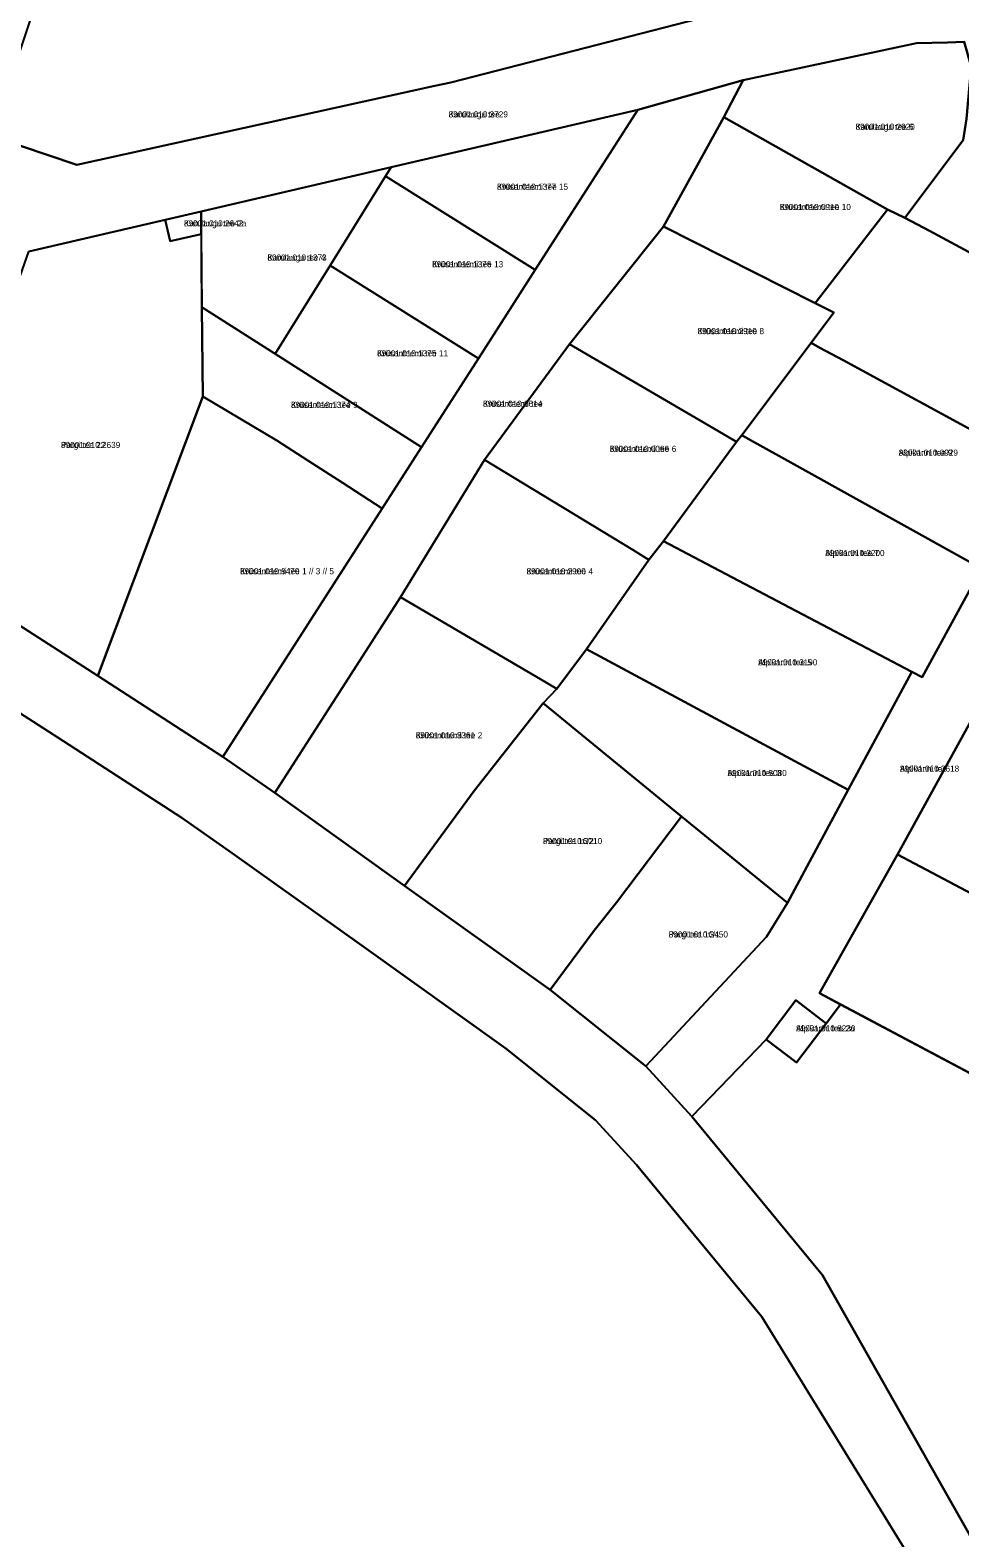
# Model space of a CAD drawing. Extents: x 526849 to 562296, y 6591741 to 6618546.
# Drawn here: x 546990.7 to 547218.3, y 6596402.5 to 6596771.5 of the extents above; entities that cross this region are included whole.
import ezdxf

# ---------------------------------------------------------------- set-up
doc = ezdxf.new("R2010")
doc.units = 0
for name, color, linetype in [('L_AADRESS', 7, 'Continuous'), ('PIIR', 7, 'Continuous'), ('TUNNUS', 7, 'Continuous')]:
    doc.layers.add(name, color=color, linetype=linetype)

msp = doc.modelspace()

# ---------------------------------------------------------------- linework, layer by layer
at = {"layer": 'PIIR'}
for points in [[(547061.75, 6596946.48), (547186.72, 6596892.31), (547160.53, 6596779.59), (547159.62, 6596775.69), (547093.73, 6596758.73), (547089.82, 6596757.87), (547002.16, 6596738.57), (546981.31, 6596745.56), (547032.18, 6596898.67)], [(547165.31, 6596759.28), (547207.75, 6596768.33), (547215.28, 6596768.54), (547219.38, 6596768.66), (547221.14, 6596762.67), (547219.94, 6596749.86), (547219.13, 6596744.63), (547204.87, 6596725.62), (547200.62, 6596727.66), (547160.53, 6596750.27)], [(547219.94, 6596749.86), (547221.14, 6596762.67), (547223.71, 6596763), (547250.81, 6596766.42), (547274.85, 6596760.13), (547256.37, 6596728.15), (547242.55, 6596705.37), (547210.88, 6596722.39), (547204.87, 6596725.62), (547219.13, 6596744.63)], [(547037.89, 6596593.65), (547076.95, 6596654.43), (547086.56, 6596669.47), (547100.49, 6596691.19), (547114.39, 6596712.87), (547139.51, 6596752.04), (547165.31, 6596759.28), (547160.53, 6596750.27), (547145.81, 6596723.49), (547122.79, 6596694.68), (547101.97, 6596666.36), (547081.4, 6596632.76), (547050.6, 6596584.83)], [(547079.14, 6596737.98), (547139.51, 6596752.04), (547114.39, 6596712.87), (547077.77, 6596735.78)], [(547200.62, 6596727.66), (547182.94, 6596704.73), (547145.81, 6596723.49), (547160.53, 6596750.27)], [(547331.64, 6596741.42), (547407.78, 6596725.43), (547411.71, 6596686.07), (547384.86, 6596637.5), (547353.74, 6596639.24), (547342.52, 6596590.2), (547325.97, 6596533.76), (547310.38, 6596483.25), (547295.96, 6596486.54), (547222.61, 6596399.92), (547184.73, 6596466.78), (547152.75, 6596505.65), (547170.93, 6596524.5), (547178.36, 6596518.85), (547185.58, 6596528.42), (547189.1, 6596533.06), (547262.13, 6596494.24), (547270.47, 6596534.11), (547284.34, 6596584.38), (547297.37, 6596630.81), (547280.61, 6596639.69), (547294.38, 6596665.52), (547304.56, 6596660.01), (547315.27, 6596697.05)], [(547032.59, 6596727.14), (547079.14, 6596737.98), (547077.77, 6596735.78), (547064.19, 6596713.91), (547050.74, 6596692.27), (547032.8, 6596703.7)], [(547077.77, 6596735.78), (547114.39, 6596712.87), (547100.49, 6596691.19), (547064.19, 6596713.91)], [(547023.81, 6596725.12), (547032.59, 6596727.14), (547032.61, 6596721.61), (547025.04, 6596719.85)], [(547184.09, 6596693.8), (547181.91, 6596695.01), (547187.49, 6596702.43), (547182.94, 6596704.73), (547200.62, 6596727.66), (547204.87, 6596725.62), (547210.88, 6596722.39), (547242.55, 6596705.37), (547255.38, 6596698.36), (547237.2, 6596664.95), (547189.8, 6596690.72)], [(546990.46, 6596717.38), (547023.81, 6596725.12), (547025.04, 6596719.85), (547032.61, 6596721.61), (547032.8, 6596703.7), (547032.98, 6596681.88), (547007.29, 6596613.51), (546963.62, 6596641.59)], [(547145.81, 6596723.49), (547182.94, 6596704.73), (547187.49, 6596702.43), (547181.91, 6596695.01), (547164.92, 6596672.42), (547163.69, 6596670.76), (547159.06, 6596673.47), (547122.79, 6596694.68)], [(547064.19, 6596713.91), (547100.49, 6596691.19), (547086.56, 6596669.47), (547050.74, 6596692.27)], [(547032.8, 6596703.7), (547050.74, 6596692.27), (547086.56, 6596669.47), (547076.95, 6596654.43), (547067.16, 6596660.79), (547058.69, 6596666.21), (547051.16, 6596671.07), (547032.98, 6596681.88)], [(547141.45, 6596517.91), (547170.98, 6596549.56), (547176.1, 6596557.9), (547191.03, 6596585.61), (547206.58, 6596614.49), (547209.07, 6596613.2), (547223.59, 6596639.73), (547237.2, 6596664.95), (547255.38, 6596698.36), (547265.89, 6596692.62), (547260.92, 6596683.48), (547258.55, 6596684.78), (547244.58, 6596658.55), (547220.84, 6596613.65), (547225.89, 6596611.32), (547203.04, 6596569.78), (547183.99, 6596535.77), (547189.1, 6596533.06), (547185.58, 6596528.42), (547178.14, 6596534.06), (547170.93, 6596524.5), (547152.75, 6596505.65)], [(547122.79, 6596694.68), (547159.06, 6596673.47), (547163.69, 6596670.76), (547145.75, 6596646.48), (547142.19, 6596641.92), (547138.26, 6596644.31), (547101.97, 6596666.36)], [(547181.91, 6596695.01), (547184.09, 6596693.8), (547189.8, 6596690.72), (547237.2, 6596664.95), (547223.59, 6596639.73), (547174.05, 6596667.33), (547167.06, 6596671.2), (547164.92, 6596672.42)], [(547007.33, 6596613.48), (547032.98, 6596681.88), (547051.16, 6596671.07), (547058.69, 6596666.21), (547067.16, 6596660.79), (547076.95, 6596654.43), (547037.89, 6596593.65)], [(547164.92, 6596672.42), (547167.06, 6596671.2), (547174.05, 6596667.33), (547223.59, 6596639.73), (547209.07, 6596613.2), (547206.58, 6596614.49), (547154.77, 6596641.74), (547145.75, 6596646.48), (547163.69, 6596670.76)], [(547101.97, 6596666.36), (547138.26, 6596644.31), (547142.19, 6596641.92), (547126.93, 6596620), (547119.67, 6596610.3), (547115.7, 6596612.63), (547081.4, 6596632.76)], [(547126.93, 6596620), (547142.19, 6596641.92), (547145.75, 6596646.48), (547154.77, 6596641.74), (547206.58, 6596614.49), (547191.03, 6596585.61), (547135.74, 6596615.26)], [(547081.4, 6596632.76), (547115.7, 6596612.63), (547119.67, 6596610.3), (547116.33, 6596606.8), (547099.45, 6596585.34), (547082.41, 6596562.08), (547050.6, 6596584.83)], [(547124.06, 6596600.46), (547116.33, 6596606.8), (547119.67, 6596610.3), (547126.93, 6596620), (547135.74, 6596615.26), (547191.03, 6596585.61), (547176.1, 6596557.9), (547150.16, 6596579.05)], [(547225.89, 6596611.32), (547284.3, 6596584.39), (547270.48, 6596534.11), (547203.04, 6596569.78)], [(547099.45, 6596585.34), (547116.33, 6596606.8), (547124.06, 6596600.46), (547150.16, 6596579.05), (547134.25, 6596558), (547128.78, 6596551.14), (547118.02, 6596536.62), (547082.41, 6596562.08)], [(547176.1, 6596557.9), (547170.98, 6596549.56), (547141.45, 6596517.91), (547118.02, 6596536.62), (547128.78, 6596551.14), (547134.25, 6596558), (547150.16, 6596579.05)], [(547203.04, 6596569.78), (547270.48, 6596534.11), (547262.14, 6596494.26), (547183.99, 6596535.77)], [(547185.58, 6596528.42), (547178.36, 6596518.85), (547170.93, 6596524.5), (547178.14, 6596534.06)]]:
    msp.add_lwpolyline(points, close=True, dxfattribs=at)
for points in [[(546981.31, 6596745.56), (547002.16, 6596738.57), (547089.82, 6596757.87), (547093.73, 6596758.73), (547159.62, 6596775.69)], [(547256.48, 6596774.41), (547280.96, 6596768.02), (547281.06, 6596767.99), (547274.85, 6596760.13), (547250.81, 6596766.42), (547221.14, 6596762.67), (547219.38, 6596768.66), (547215.28, 6596768.54), (547207.75, 6596768.33), (547165.31, 6596759.28), (547139.51, 6596752.04), (547079.14, 6596737.98), (547032.59, 6596727.14), (547023.81, 6596725.12), (546990.46, 6596717.38)], [(546963.62, 6596641.59), (547007.29, 6596613.51), (547037.89, 6596593.65), (547050.6, 6596584.83), (547082.41, 6596562.08), (547118.02, 6596536.62), (547141.45, 6596517.91), (547152.75, 6596505.65), (547184.73, 6596466.78), (547222.61, 6596399.92)], [(547211.44, 6596388.93), (547169.84, 6596456.55), (547139.17, 6596493.82), (547129.15, 6596504.7), (547107.16, 6596522.26), (547071.94, 6596547.44), (547040.23, 6596570.11), (547027.86, 6596578.7), (546997.52, 6596598.39), (546944.59, 6596632.43)], [(546944.59, 6596632.43), (546997.52, 6596598.39), (547027.86, 6596578.7), (547040.23, 6596570.11), (547071.94, 6596547.44), (547107.16, 6596522.26), (547129.15, 6596504.7), (547139.17, 6596493.82), (547169.84, 6596456.55), (547211.44, 6596388.93)]]:
    msp.add_lwpolyline(points, dxfattribs=at)

# ---------------------------------------------------------------- texts
at = {"layer": 'L_AADRESS'}
for s, p in [('Karulaugu tee', (547093.19, 6596750.17)), ('Karulaugu tee 6', (547192.8, 6596747.14)), ('Krüsanteemi tee 15', (547105.02, 6596732.46)), ('Krüsanteemi tee 10', (547174.26, 6596727.5)), ('Karulaugu tee 2a', (547028.4, 6596723.5)), ('Karulaugu tee 4', (547048.82, 6596715.12)), ('Krüsanteemi tee 13', (547089.14, 6596713.49)), ('Krüsanteemi tee 8', (547154.12, 6596697.12)), ('Krüsanteemi tee 11', (547075.67, 6596691.69)), ('Krüsanteemi tee 9', (547054.6, 6596679.07)), ('Krüsanteemi tee', (547101.6, 6596679.34)), ('Pargi tee 22', (546998.3, 6596669.25)), ('Krüsanteemi tee 6', (547132.63, 6596668.3)), ('Alpikanni tee 9', (547203.36, 6596667.37)), ('Alpikanni tee 7', (547185.4, 6596642.81)), ('Krüsanteemi tee 1 // 3 // 5', (547042.14, 6596638.35)), ('Krüsanteemi tee 4', (547112.25, 6596638.33)), ('Alpikanni tee 5', (547168.95, 6596616.04)), ('Krüsanteemi tee 2', (547085.14, 6596598.18)), ('Alpikanni tee 3', (547161.45, 6596588.95)), ('Alpikanni tee', (547203.67, 6596590.01)), ('Pargi tee 16/2', (547116.28, 6596572.3)), ('Pargi tee 16/1', (547147.06, 6596549.44)), ('Alpikanni tee 2a', (547178.25, 6596526.45))]:
    msp.add_text(s, height=1.5, dxfattribs=at).set_placement(p)
at = {"layer": 'TUNNUS'}
for s, p in [('89001:010:3729', (547093.19, 6596750.17)), ('89001:010:2920', (547192.8, 6596747.14)), ('89001:010:1377', (547105.02, 6596732.46)), ('89001:010:0910', (547174.26, 6596727.5)), ('89001:010:2642', (547028.4, 6596723.5)), ('89001:010:1373', (547048.82, 6596715.12)), ('89001:010:1376', (547089.14, 6596713.49)), ('89001:010:2910', (547154.12, 6596697.12)), ('89001:010:1375', (547075.67, 6596691.69)), ('89001:010:1374', (547054.6, 6596679.07)), ('89001:010:3614', (547101.6, 6596679.34)), ('89001:010:2639', (546998.3, 6596669.25)), ('89001:010:0066', (547132.63, 6596668.3)), ('89001:010:0929', (547203.36, 6596667.37)), ('89001:010:3200', (547185.4, 6596642.81)), ('89001:010:9470', (547042.14, 6596638.35)), ('89001:010:2900', (547112.25, 6596638.33)), ('89001:010:3190', (547168.95, 6596616.04)), ('89001:010:3361', (547085.14, 6596598.18)), ('89001:010:5080', (547161.45, 6596588.95)), ('89001:010:3618', (547203.67, 6596590.01)), ('89001:010:3210', (547116.28, 6596572.3)), ('89001:010:3450', (547147.06, 6596549.44)), ('89001:010:8230', (547178.25, 6596526.45))]:
    msp.add_text(s, height=1.5, dxfattribs=at).set_placement(p)

doc.saveas('drawing.dxf')
